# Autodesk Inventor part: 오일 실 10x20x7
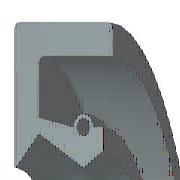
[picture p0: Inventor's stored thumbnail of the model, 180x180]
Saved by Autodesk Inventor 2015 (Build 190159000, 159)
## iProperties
IsCustomPart: 1
Created: 2012-02
Part Number: 오일 실 10x20x7
Material: 고무
Description: 오일-실
Document SubType Name: Modeling
Standard: KS B 2804
Designer: mduedu
Standards Organization: KS
Language: ko-KR
Size Designation: D - 10 20 7
Categories: <MemberInstance><Categories><Category DisplayName="샤프트 부품" InternalName="7f7aeb1f-a693-4053-b835-cee3144e0d98" Mnemonic="SHFT"><Category DisplayName="실링" Intern
Density: 0.93 g/cm^3
Appearance: 고무 - 검은색 - 버전 1.1
Author: mduedu
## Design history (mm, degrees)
revolve "본체" stored, may be unused: angle "d17" = 90 deg
revolve "스프링1" stored, may be unused: angle "d18" = 90 deg
body "Solid1"
sketch "스케치1"
  geometry: L1 (0, 10)-(7, 10); L2 (7, 8.25)-(1.75, 8.25); L3 (1.75, 6.75)-(4.9, 5); L4 (4.9, 5)-(0, 5); L5 (0, 0)-(9.586, 0) reference; L6 (4.9, 5)-(6.3, 5.875); L7 (0, 18)-(0, -3) reference; L8 (-1.941, 0)-(11.507, 0) reference; L9 (4.2, 7.1)-(1.75, 7.59); L10 (1.75, 7.59)-(1.75, 8.25); L11 (0, 10)-(0, 5.088); L12 (4.9, 5)-(0, 5); L13 (1.75, 6.75)-(0.152, 5.028); L14 (7, 10)-(7, 8.25); L15 (5.6, 7.1)-(6.3, 7.1); L16 (6.3, 7.1)-(6.3, 5.875); C1 r 0.455 at (4.9, 7.1); A1 r 0.7 centre (4.9, 7.1) between (5.6, 7.1) and (4.2, 7.1); A2 r 0.088 centre (0.088, 5.088) between (0, 5.088) and (0.152, 5.028); 1 further point
  constraints: 28 end point, 5 horizontal alignment, 5 point on line, 4 point on circle, 4 vertical alignment, 3 centre point, 3 tangent, 2 collinear, 2 horizontal, 2 perpendicular, 1 coincident, 1 parallel
  dimensions: "d0" = 20 diameter of L1 L5 (= SD2); "d1" = 1.75 distance of L1.end L2.start (= SD); "d2" = 0.91 diameter of C1 (= SPDI); "d3" = 1.4 diameter of A1 (= SPDA); "d4" = 10 diameter of L3.end L5 (= NND); "d5" = 13.5 diameter of L3.start L5 (= TKDM); "d7" = 15.18 diameter of L9.end L5 (= TKDM + 0.24 x SWDT); "d8" = 1.75 distance between parallel lines of L11 L10 (= SD); "d9" = 4.9 distance from line of L11 C1.centre (= SPDST); "d10" = 14.2 diameter of C1.centre L5 (= HLDM); "d11" = 0.0875 radius of A2 (= 0.25 x LAB); "d12" = 6.3 distance between parallel lines of L11 L16 (= SDI); "d13" = 11.75 diameter of L6.end L5 (= ABDM); "d14" = 7 distance from line of L11 L1.end (= SWDT)
fillet "모깎기1" dims "d6" = 0.3 (= RR)
other parameters: "SD2" = 20 [user parameter; used in 1 equation term], "SWDT" = 7 [user parameter; used in 2 equation terms], "RR" = 0.3 [user parameter; used in 1 equation term], "SD" = 1.75 [user parameter; used in 2 equation terms], "NND" = 10 [user parameter; used in 1 equation term], "SPDA" = 1.4 [user parameter; used in 1 equation term], "SPDI" = 0.91 [user parameter; used in 1 equation term], "TKDM" = 13.5 [user parameter; used in 2 equation terms], "HLDM" = 14.2 [user parameter; used in 1 equation term], "ABDM" = 11.75 [user parameter; used in 1 equation term], "SDI" = 6.3 [user parameter; used in 1 equation term], "SPDST" = 4.9 [user parameter; used in 1 equation term], "LAB" = 0.35 [user parameter; used in 1 equation term], "d15" = 0, "d16" = 0, "d19" = 0
